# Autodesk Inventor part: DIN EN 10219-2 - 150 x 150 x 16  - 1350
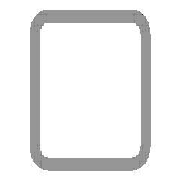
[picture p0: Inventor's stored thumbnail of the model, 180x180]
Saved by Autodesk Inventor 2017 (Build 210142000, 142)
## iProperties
_CCFamilyMember: 76
_CCFamilyDisplayName: DIN EN 10219-2 (Square Hollow Section - Cold Formed) - Cold formed welded structural hollow sections of non-alloy and fine grain structural steel
_FrameMemberDoc: Frame Member File
_Version: 15.0.0
_GetPNFromCC: 1
Created: 2017-11
Part Number: DIN EN 10219-2 - 150 x 150 x 16  - 1350
Material: Steel, Mild
Description: Cold formed welded structural hollow sections of non-alloy and fine grain structural steel
Document SubType Name: Modeling
Standard: DIN
Designer: iusti
Standard Revision: 2006-07
Standards Organization: DIN
Language: en-US
Size Designation: 150 x 150 x 16
Categories: <MemberInstance><Categories><Category DisplayName="Structural Shapes" InternalName="089c4875-fa83-4c05-b084-43b9cc11f5ed" Mnemonic="GRDR"><CategoryParameter Dis
Stock Number: 150 x 150 x 16
Mass: 79240 g
Surface Area: 12767.4 cm^2
Volume: 10094.3 cm^3
Density: 7.85 g/cm^3
Appearance: Semi-Polished
IsCustomPart: 1
G_L: 1350.000 mm
G_W: 150.000 mm
G_H: 150.000 mm
+5245FDE4-FC26-48DD-8D5F-DB9AF3ABDA78+CUTDETAIL1: Cut
+5EC8F8CE-D404-4871-B3D9-14F147CC6C7E+CUTDETAIL2: Cut
Author: iusti
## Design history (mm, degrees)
node "Start plane"
node "End plane"
sketch "Sketch"
  geometry: L1 (-75, -27)-(-75, 27); L2 (-27, 75)-(27, 75); L3 (75, 27)-(75, -27); L4 (27, -75)-(-27, -75); L5 (-27, 59)-(27, 59); L6 (59, 27)-(59, -27); L7 (27, -59)-(-27, -59); L8 (-59, -27)-(-59, 27); L9 (0, 118.918)-(0, -118.918) reference; L10 (-118.918, 0)-(118.918, 0) reference; A1 r 48 centre (-27, -27) between (-75, -27) and (-27, -75); A2 r 48 centre (-27, 27) between (-27, 75) and (-75, 27); A3 r 48 centre (27, 27) between (75, 27) and (27, 75); A4 r 48 centre (27, -27) between (27, -75) and (75, -27); A5 r 32 centre (-27, 27) between (-27, 59) and (-59, 27); A6 r 32 centre (27, 27) between (59, 27) and (27, 59); A7 r 32 centre (27, -27) between (27, -59) and (59, -27); A8 r 32 centre (-27, -27) between (-59, -27) and (-27, -59)
  constraints: 16 end point, 16 point on circle, 8 centre point, 8 tangent, 4 parallel, 3 equal radius, 2 perpendicular, 7 other
  dimensions: "d7" = 48 radius of A1 (= G_IR); "d10" = 150 distance between parallel lines of L2 L4 (= G_H); "d11" = 150 distance between parallel lines of L1 L3 (= G_W); "d12" = 16 distance between parallel lines of L3 L6 (= G_T); "d15" = 75 distance between parallel lines of L2 L10 (= 0.5 x d10); "d16" = 75 distance between parallel lines of L9 L3 (= 0.5 x d11)
extrude "Body" new body sketch "Sketch" stored distance "d3" = 1350 (= G_L); taper "d4" = 0 deg
node "Driven Length"
  sketch "Sketch3"
    geometry: L1 (0, 0)-(10, 0) reference
    constraints: 2 end point, 1 horizontal
  workplane "Work Plane3"
  sketch "Sketch4"
    geometry: L1 (-2, 75)-(12, 75) reference; L2 (-2, 1425)-(12, 1425) reference
    dimensions: "d18" = 1350 distance between parallel lines of L1 L2 (derived)
workplane "Work Plane4"
split "Split1"
workplane "Work Plane5"
split "Split2"
body "Solid1"
other parameters: "G_W" = 150 [user parameter; used in 1 equation term], "G_H" = 150 [user parameter; used in 1 equation term], "G_T" = 16 [user parameter; used in 1 equation term], "G_IR" = 48 [user parameter; used in 1 equation term], "G_L" = 1350 (= d18) [user parameter; used in 1 equation term], "G_OFFSET_START" = -75 [user parameter; used in 1 equation term], "G_OFFSET_END" = -75 [user parameter; used in 1 equation term], "d13" = 75 (= -G_OFFSET_START), "d14" = 1425 (= G_OFFSET_END + B_L), "d17" = 90 deg
